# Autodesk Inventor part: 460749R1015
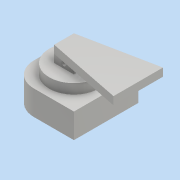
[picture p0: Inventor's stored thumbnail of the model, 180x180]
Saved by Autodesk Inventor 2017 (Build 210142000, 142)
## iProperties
Created: 2016-07
Part Number: 460749R1015
Material: Aluminum 6061
Document SubType Name: Modeling
Designer: Polytech
Density: 2.7 g/cm^3
Appearance: Aluminum - Flat
Mass: 1260.26 g
Surface Area: 611.154 cm^2
Volume: 466.762 cm^3
Author: Polytech
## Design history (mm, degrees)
sketch "Sketch1"
  geometry: C1 r 23 at (0, 0); 1 further point
  constraints: 1 centre point, 1 coincident
  dimensions: "d0" = 46 diameter of C1
extrude "Extrusion1" new body sketch "Sketch1" distance "d1" = 18; taper "d2" = 0 deg
sketch "Sketch2"
  geometry: L1 (-11.75, 48.75)-(48.75, 48.75); L2 (48.75, 48.75)-(48.75, -48.75); L3 (48.75, -48.75)-(-11.75, -48.75); L4 (-48.75, -11.75)-(-48.75, 11.75); L5 (-48.75, 48.75)-(48.75, -48.75); L6 (48.75, 48.75)-(-48.75, -48.75); A1 r 37 centre (-11.75, 11.75) between (-11.75, 48.75) and (-48.75, 11.75); A2 r 37 centre (-11.75, -11.75) between (-48.75, -11.75) and (-11.75, -48.75); 1 further point
  constraints: 12 end point, 4 point on circle, 4 point on line, 4 tangent, 2 centre point, 2 midpoint, 2 parallel, 1 equal radius, 1 horizontal, 1 perpendicular
  dimensions: "d3" = 97.5 distance of L2.end L6.end; "d4" = 97.5 distance of L1.end L2.end; "d5" = 37 radius of A1
extrude "Extrusion2" join sketch "Sketch2" distance "d6" = 37.5; taper "d7" = 0 deg
sketch "Sketch3"
  geometry: C1 r 37.5 at (0, 0); 1 further point
  constraints: 1 centre point, 1 coincident
  dimensions: "d8" = 75 diameter of C1
extrude "Extrusion3" join sketch "Sketch3" distance "d9" = 15; taper "d10" = 0 deg
sketch "Sketch4"
  geometry: L1 (-15, 15)-(15, 15); L2 (15, 15)-(15, -15); L3 (15, -15)-(-15, -15); L4 (-15, -15)-(-15, 15); L5 (-15, 15)-(15, -15); L6 (15, 15)-(-15, -15); 1 further point
  constraints: 12 end point, 2 midpoint, 2 parallel, 1 horizontal, 1 perpendicular
  dimensions: "d11" = 30 distance of L2.end L3.end; "d12" = 30 distance of L1.end L2.end
extrude "Extrusion4" join sketch "Sketch4" distance "d13" = 12; taper "d14" = 0 deg
sketch "Sketch5"
  geometry: L1 (-15, 6)-(15, 6); L2 (15, 6)-(15, -6); L3 (15, -6)-(-15, -6); L4 (-15, -6)-(-15, 6); L5 (-15, 6)-(15, -6); L6 (15, 6)-(-15, -6); 1 further point
  constraints: 12 end point, 2 midpoint, 2 parallel, 1 horizontal, 1 perpendicular
  dimensions: "d15" = 30 distance of L2.end L3.end; "d16" = 12 distance of L1.end L2.end
extrude "Extrusion5" cut sketch "Sketch5" distance "d17" = 12; taper "d18" = 0 deg
sketch "Sketch6"
  geometry: L1 (52.5, 0)-(-22.5, 0) reference; C1 r 3 at (15, 6); 1 further point
  constraints: 1 centre point, 1 vertical alignment
  dimensions: "d19" = 6 diameter of C1; "d20" = 6 distance from line of L1 C1.centre
extrude "Extrusion6" cut sketch "Sketch6" stored distance "d21" = 12; taper "d22" = 0 deg
sketch "Sketch7"
  geometry: L1 (-15, 15)-(-15, -15); L2 (-15, -15)-(97.5, -37.5); L3 (97.5, -37.5)-(97.5, 37.5); L4 (97.5, 37.5)-(-15, 15); 4 further points
  constraints: 8 end point, 2 coincident, 1 horizontal alignment, 1 midpoint, 1 parallel, 1 vertical
  dimensions: "d23" = 75 distance of L2.end L3.end; "d24" = 97.5 horizontal distance of L2.end point (0, 0)
extrude "Extrusion7" join sketch "Sketch7" distance "d25" = 12; taper "d26" = 0 deg
sketch "Sketch8"
  geometry: C1 r 23 at (0, 0); 1 further point
  constraints: 1 centre point, 1 coincident
  dimensions: "d27" = 46 diameter of C1
extrude "Extrusion8" cut sketch "Sketch8" distance "d28" = 24.5; taper "d29" = 0 deg
body "Solid1"
